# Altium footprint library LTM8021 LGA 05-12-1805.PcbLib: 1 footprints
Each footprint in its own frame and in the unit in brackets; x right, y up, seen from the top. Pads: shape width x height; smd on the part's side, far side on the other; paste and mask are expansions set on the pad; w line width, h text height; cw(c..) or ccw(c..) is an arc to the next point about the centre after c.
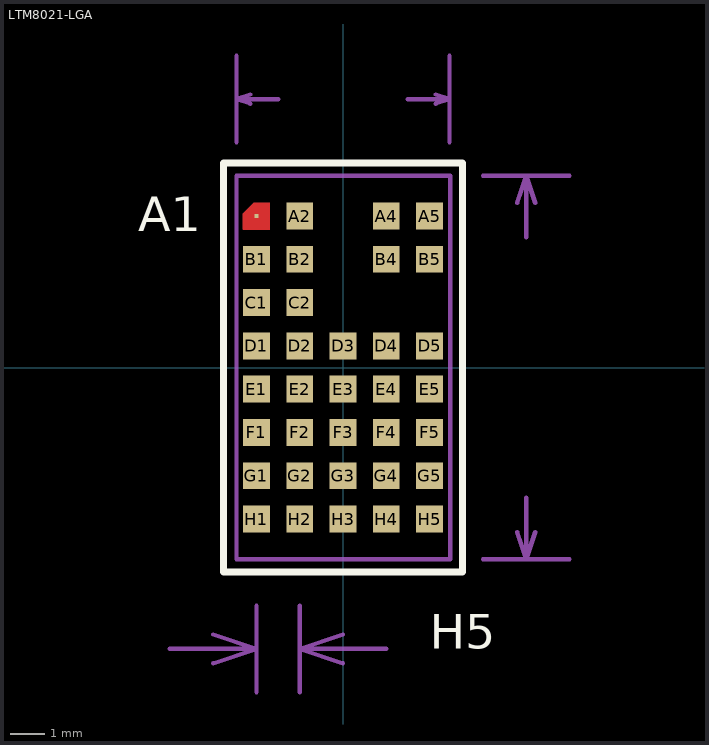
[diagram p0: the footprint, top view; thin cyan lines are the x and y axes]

## LTM8021-LGA [mil]
pads (35):
  rect 5x5 smd paste-3.5 mask-3: A1(-100,175)
  rect 31x31 smd paste-3.5 mask-3: A2(-50,175) A4(50,175) A5(100,175) B1(-100,125) B2(-50,125) B4(50,125) B5(100,125) C1(-100,75) C2(-50,75) D1(-100,25) D2(-50,25) D3(0,25) D4(50,25) D5(100,25) E1(-100,-25) E2(-50,-25) E3(0,-25) E4(50,-25) E5(100,-25) F1(-100,-75) F2(-50,-75) F3(0,-75) F4(50,-75) F5(100,-75) G1(-100,-125) G2(-50,-125) G3(0,-125) G4(50,-125) G5(100,-125) H1(-100,-175) H2(-50,-175) H3(0,-175) H4(50,-175) H5(100,-175)
TopLayer:
  region: -115.5,159.5 -84.5,159.5 -84.5,190.5 -102.5,190.5 -115.5,177.5
  lines w0.39: -115.5,159.5 -84.5,159.5 -84.5,190.5 -102.5,190.5 -115.5,177.5 -115.5,159.5
TopOverlay:
  lines w8: -137.8,-236.22 137.8,-236.22 137.8,236.22 -137.8,236.22 -137.8,-236.22
  text "H5" at 100,-325 h40
  text "A1" at -236.22,157.48 h40
Mechanical16:
  lines w5: -200,-325 -100,-325 ; -150,-341.67 -100,-325 ; -150,-308.33 -100,-325 ; -123.03,260.04 -123.03,360.04 ; -107.28,304.79 -123.03,310.04 ; -107.28,315.29 -123.03,310.04 ; -100,-375 -100,-275 ; -74.94,310.04 -123.03,310.04 ; -50,-375 -50,-275 ; 0,-341.67 -50,-325 ; 0,-308.33 -50,-325 ; 50,-325 -50,-325 ; 74.94,310.04 123.03,310.04 ; 107.28,304.79 123.03,310.04 ; 107.28,315.29 123.03,310.04 ; 123.03,-221.46 -123.03,-221.46 -123.03,221.46 124.02,221.46 124.02,-221.46 ; 123.03,260.04 123.03,360.04 ; 161.61,-221.46 261.61,-221.46 ; 161.61,221.46 261.61,221.46 ; 201.12,-189.96 211.61,-221.46 ; 201.12,189.96 211.61,221.46 ; 211.61,-150.38 211.61,-221.46 ; 211.61,150.38 211.61,221.46 ; 222.11,-189.96 211.61,-221.46 ; 222.11,189.96 211.61,221.46
  text "1.27 (mm)" at -275.77,-444.97 h50
  text "11.25 (mm)" at 231.29,-140.38 h31.5
  text "6.25 (mm)" at -64.94,300.2 h15.75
